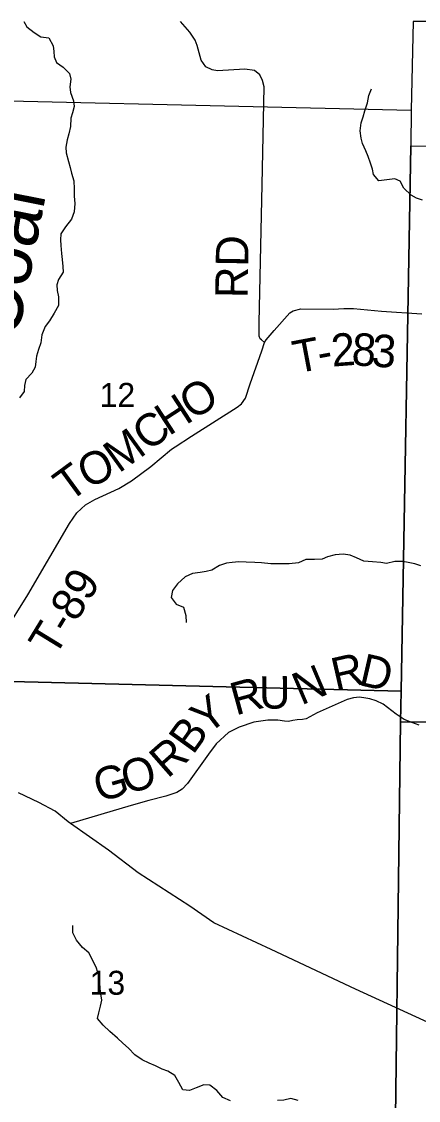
# Model space of a CAD drawing. Extents: x -452339 to 6403467, y -1 to 1814750.
# Drawn here: x -63350 to -59685, y 1553189 to 1563141 of the extents above; entities that cross this region are included whole.
import ezdxf

# ---------------------------------------------------------------- set-up
doc = ezdxf.new("R2010")
doc.units = 0
for name, color, linetype in [('GM_X_Corporation', 7, 'Continuous'), ('GM_X_County', 7, 'Continuous'), ('GM_X_County_Road', 7, 'Continuous'), ('GM_X_County_ROW', 7, 'Continuous'), ('GM_X_Major_Lake', 7, 'Continuous'), ('GM_X_Major_Lake_Text', 7, 'Continuous'), ('GM_X_Section', 7, 'Continuous'), ('GM_X_Township_Road_Text', 7, 'Continuous'), ('GM_X_Unincorporated_Location', 7, 'Continuous')]:
    doc.layers.add(name, color=color, linetype=linetype)

msp = doc.modelspace()

# ---------------------------------------------------------------- linework, layer by layer
at = {"layer": 'GM_X_County_Road'}
msp.add_lwpolyline([(-54074.7, 1551143.3), (-54513.9, 1551239.4), (-54956.8, 1551325.5), (-54974.4, 1551328.9), (-55147.6, 1551404.8), (-55304.2, 1551468.2), (-55789.9, 1551712.4), (-56093.5, 1551969.6), (-56575.7, 1552330.2), (-56923.3, 1552585.2), (-57634, 1552984.7), (-58523.1, 1553391.5), (-59488.6, 1553858), (-60265.3, 1554215.2), (-61046.1, 1554582.4), (-61573.9, 1554828.5), (-61796.9, 1554979.8), (-62272.9, 1555288.4), (-62548.2, 1555497.6), (-62897.5, 1555742.9), (-62919.8, 1555758.6), (-63040.4, 1555856.3), (-63191, 1555935.7), (-63379.6, 1556027.1)], dxfattribs=at)
at = {"layer": 'GM_X_County_ROW'}
for points in [[(-63733, 1557152), (-63291.2, 1557851.4), (-62908.7, 1558509.6), (-62838.4, 1558609.1), (-62759.7, 1558682.6), (-62674.6, 1558732.3), (-62452.4, 1558832.5), (-62335.6, 1558904.7), (-62155.9, 1559036.2), (-61966.8, 1559195.9), (-61931.2, 1559218.6), (-61780.9, 1559317.5), (-61359.6, 1559583.6), (-61320.1, 1559614.4), (-61281, 1559667.2), (-61239.3, 1559798.2), (-61132.6, 1560102.7), (-61108, 1560179.3), (-61134.4, 1560204.8), (-61146.5, 1560212.6), (-61157, 1560238.5), (-61155.2, 1560364.8), (-61129.2, 1561635.6), (-61110.9, 1562537.5), (-61123.9, 1562597.4), (-61150.8, 1562649), (-61199.5, 1562690.2), (-61287.7, 1562702.6), (-61539.4, 1562686.1), (-61589.5, 1562695.2), (-61648, 1562724.2), (-61693, 1562783.5), (-61729.4, 1562921.1), (-61746.3, 1562968.9), (-61797.5, 1563042.1), (-61883.2, 1563140.5)], [(-61108, 1560179.3), (-61092.4, 1560205.6), (-61017.9, 1560291.1), (-60872.8, 1560454), (-60843.1, 1560472.6), (-60771.4, 1560491.9), (-60471.4, 1560487.3), (-60375.5, 1560495), (-60283.6, 1560494.7), (-60027.1, 1560469.2), (-59652.8, 1560443.9)]]:
    msp.add_lwpolyline(points, dxfattribs=at)
at = {"layer": 'GM_X_Section'}
msp.add_lwpolyline([(-59677.9, 1556650.5), (-59746.4, 1556675.3), (-59816.8, 1556702.1), (-59891.7, 1556750.9), (-60011.3, 1556842.9), (-60075.8, 1556875.8), (-60134.1, 1556892.8), (-60172.2, 1556900.2), (-60228.4, 1556907.2), (-60284.3, 1556902.1), (-60344, 1556887), (-60619.9, 1556763.8), (-60723, 1556709.9), (-60756.9, 1556703.3), (-60804.8, 1556700.4), (-60844.7, 1556693.7), (-60884.6, 1556684.9), (-60922.6, 1556686.3), (-60982.7, 1556695.2), (-61074.8, 1556697.6), (-61206.4, 1556677.2), (-61339.6, 1556630.7), (-61438.8, 1556582.8), (-61553, 1556478.5), (-61625.4, 1556383), (-61818.7, 1556113), (-61867.8, 1556060), (-61915.3, 1556029.1), (-62016.7, 1555995.2), (-62174.1, 1555956.3), (-62339.3, 1555909.2), (-62897.5, 1555742.9)], dxfattribs=at)
at = {"layer": 'GM_X_Township_Road_Text'}
for points in [[(-63330.5, 1563140.5), (-63301.6, 1563091), (-63233.5, 1563041.2), (-63171.4, 1563001.3), (-63099.3, 1562989.6), (-63059.1, 1562917.6), (-63053, 1562865.6), (-63048.8, 1562815.6), (-63028.7, 1562763.6), (-62964.6, 1562719.7), (-62906.4, 1562661.9), (-62896.3, 1562607.8), (-62904.1, 1562537.7), (-62897.9, 1562485.7), (-62871.7, 1562409.7), (-62865.5, 1562357.7), (-62879.4, 1562299.6), (-62895.2, 1562249.5), (-62899, 1562171.4), (-62912.8, 1562105.2), (-62928.6, 1562051.1), (-62940.4, 1561983), (-62938.2, 1561931), (-62916, 1561850.9), (-62901.8, 1561794.9), (-62887.7, 1561742.9), (-62867.5, 1561670.9), (-62863.2, 1561598.8), (-62863, 1561528.7), (-62858.8, 1561462.7), (-62864.6, 1561384.6), (-62890.4, 1561316.4), (-62944.1, 1561246.1), (-62987.9, 1561181.9), (-62989.8, 1561125.8), (-62987.6, 1561075.8), (-62981.4, 1561001.7), (-62975.2, 1560945.7), (-62969, 1560881.6), (-62964.9, 1560827.6), (-63008.6, 1560761.3), (-63024.5, 1560711.2), (-63022.3, 1560661.1), (-63008.2, 1560601.1), (-63009.9, 1560523), (-63049.7, 1560450.8), (-63091.4, 1560378.6), (-63133.3, 1560328.4), (-63163, 1560250.2)], [(-59648.2, 1561493.6), (-59702.2, 1561511.5), (-59752.3, 1561539.3), (-59820.5, 1561605.2), (-59854.7, 1561667.1), (-59904.7, 1561689), (-59976.7, 1561680.7), (-60050.6, 1561670.5), (-60100.7, 1561728.4), (-60110.9, 1561780.4), (-60127, 1561834.4), (-60149.2, 1561896.4), (-60171.4, 1561948.4), (-60201.6, 1562016.3), (-60213.7, 1562066.3), (-60223.9, 1562132.4), (-60214.1, 1562206.5), (-60196.3, 1562262.6), (-60180.5, 1562316.7), (-60154.7, 1562390.9), (-60142.9, 1562459), (-60119.1, 1562521.2)], [(-63163, 1560250.2), (-63172.8, 1560178), (-63194.6, 1560115.9), (-63212.4, 1560053.7), (-63218.2, 1560003.6), (-63224.1, 1559953.6), (-63255.9, 1559897.4), (-63309.7, 1559839.1), (-63321.5, 1559785), (-63327.4, 1559728.9), (-63369.2, 1559668.7)], [(-59661.9, 1558119.4), (-59719.9, 1558137.2), (-59779.9, 1558151), (-59830, 1558160.8), (-59903.9, 1558158.6), (-59981.8, 1558142.3), (-60031.8, 1558152.1), (-60109.8, 1558157.9), (-60189.8, 1558161.6), (-60255.9, 1558193.4), (-60315.9, 1558217.2), (-60379.9, 1558227), (-60453.9, 1558222.8), (-60523.8, 1558202.5), (-60575.7, 1558182.3), (-60645.7, 1558180), (-60725.7, 1558179.8), (-60793.5, 1558147.5), (-60879.5, 1558137.2), (-60931.4, 1558137), (-60989.4, 1558138.8), (-61049.4, 1558138.6), (-61135.4, 1558146.3), (-61197.4, 1558150.1), (-61277.4, 1558153.8), (-61343.3, 1558157.6), (-61405.3, 1558151.4), (-61457.2, 1558143.2), (-61521.2, 1558122.9), (-61593, 1558080.6), (-61644.9, 1558068.4), (-61700.9, 1558058.2), (-61770.8, 1558048), (-61838.7, 1558017.7), (-61910.5, 1557955.4), (-61956.3, 1557893.1), (-61970.1, 1557829), (-61923.9, 1557765.1), (-61853.8, 1557737.3), (-61833.6, 1557663.2), (-61831.4, 1557597.2)], [(-61422.1, 1553185), (-61492.1, 1553214.8), (-61546.3, 1553280.7), (-61612.5, 1553330.5), (-61668.4, 1553332.3), (-61736.3, 1553304), (-61800.2, 1553281.8), (-61860.2, 1553287.6), (-61898.4, 1553355.5), (-61934.6, 1553419.5), (-62000.7, 1553459.3), (-62052.7, 1553477.1), (-62114.8, 1553506.9), (-62172.8, 1553532.7), (-62236.9, 1553562.6), (-62305, 1553608.4), (-62363.2, 1553672.2), (-62415.3, 1553718.1), (-62465.4, 1553762), (-62533.6, 1553825.8), (-62595.7, 1553881.7), (-62649.9, 1553943.6), (-62636.1, 1553997.7), (-62620.3, 1554057.8), (-62608.4, 1554113.9), (-62616.6, 1554171.9), (-62624.8, 1554222), (-62626.9, 1554278), (-62641.1, 1554346.1), (-62659.3, 1554408.1), (-62691.5, 1554480), (-62729.7, 1554550), (-62785.8, 1554599.9), (-62842, 1554667.8), (-62876.2, 1554733.7), (-62876.4, 1554803.8)], [(-60796.3, 1553187.2), (-60862.4, 1553207), (-60928.3, 1553190.7), (-60988.3, 1553188.5)]]:
    msp.add_lwpolyline(points, dxfattribs=at)
at = {"layer": 'GM_X_Unincorporated_Location'}
for points in [[(-54138.3, 1563140.5), (-59734.2, 1563140.5), (-59752.5, 1562321.9), (-59755.1, 1561995.7), (-54168.4, 1561943.8)], [(-59752.5, 1562321.9), (-59755.1, 1561995.7), (-59844.9, 1556964.8), (-65186.4, 1557097.3), (-65059.8, 1562444.8)], [(-54168.4, 1561943.8), (-54249.2, 1556628.8), (-59852, 1556682.6), (-59844.9, 1556964.8), (-59755.1, 1561995.7)], [(-65186.4, 1557097.3), (-59844.9, 1556964.8), (-59852, 1556682.6), (-59917, 1551575.9), (-65238.6, 1551724.6)], [(-59852, 1556682.6), (-54249.2, 1556628.8), (-54346.1, 1551317.7), (-59917, 1551387.8), (-59917, 1551575.9)]]:
    msp.add_lwpolyline(points, close=True, dxfattribs=at)

# ---------------------------------------------------------------- texts
at = {"layer": 'GM_X_Corporation'}
msp.add_text('Coal', height=500.16, rotation=78.77792, dxfattribs=at).set_placement((-63391.1, 1560194.8))
at = {"layer": 'GM_X_County'}
for s, rotation, p in [('R', 12.83021, (-60450.8, 1556967.9)), ('D', 347.02668, (-60246, 1557022.7)), ('N', 23.04494, (-60767.6, 1556830.5)), ('R', 15.3787, (-61373.2, 1556738.5)), ('U', 0.7468, (-61155.6, 1556801)), ('Y', 37.79447, (-61638.6, 1556552.9)), ('B', 54.16027, (-61767.2, 1556369.4)), ('R', 41.31038, (-62001.6, 1556152.4)), ('O', 16.00937, (-62381.3, 1556010.8)), ('G', 15.9564, (-62635.4, 1555938.1))]:
    msp.add_text(s, height=300, rotation=rotation, dxfattribs=at).set_placement(p)
at = {"layer": 'GM_X_Major_Lake'}
for s, p in [('12', (-62629.3, 1559586.6)), ('13', (-62721.7, 1554163.6))]:
    msp.add_text(s, height=220.83, rotation=0.00001, dxfattribs=at).set_placement(p)
at = {"layer": 'GM_X_Major_Lake_Text'}
for s, rotation, p in [('RD', 89.01278, (-61263, 1560587.6)), ('T', 10.75102, (-60813.9, 1559893.7)), ('2', 4.42265, (-60481, 1559957.1)), ('8', 356.42269, (-60307.9, 1559971.3)), ('3', 356.22954, (-60123.7, 1559959.7)), ('-', 10.62253, (-60593.6, 1559935.5)), ('O', 32.55333, (-61768.7, 1559457.2)), ('H', 33.00706, (-61989.5, 1559313.7)), ('C', 37.7737, (-62178.9, 1559166.6)), ('M', 35.87045, (-62451.5, 1558969.3)), ('O', 25.24048, (-62742.6, 1558825.9)), ('T', 36.3059, (-62910.3, 1558700.8)), ('T-89', 58.55408, (-63043.7, 1557269))]:
    msp.add_text(s, height=300, rotation=rotation, dxfattribs=at).set_placement(p)

doc.saveas('drawing.dxf')
